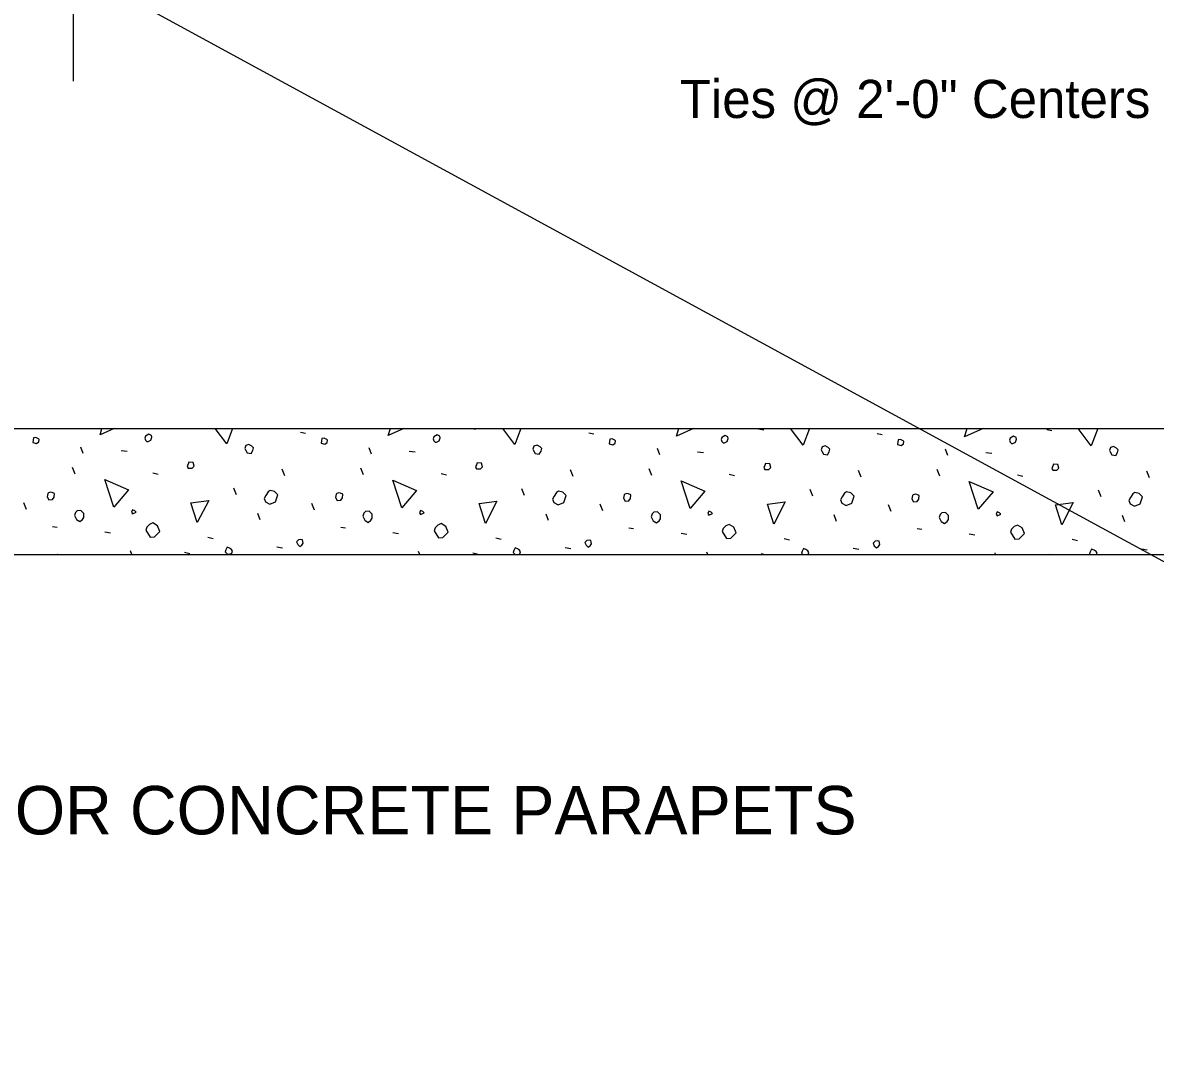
# Model space of a CAD drawing. Extents: x 110698 to 110915, y 110390 to 110472.
# Drawn here: x 110786.56 to 110792.55, y 110408.16 to 110413.66 of the extents above; entities that cross this region are included whole.
import ezdxf

# ---------------------------------------------------------------- set-up
doc = ezdxf.new("R2010")
doc.units = 0
for name, color, linetype in [('AdhocPoint_dp', 7, 'Continuous'), ('Border', 7, 'Continuous'), ('SheetBorder_dp', 7, 'Continuous'), ('SheetLines_dp', 7, 'Continuous')]:
    doc.layers.add(name, color=color, linetype=linetype)

msp = doc.modelspace()

# ---------------------------------------------------------------- linework, layer by layer
at = {"layer": 'AdhocPoint_dp'}
msp.add_line((110786.8255, 110421.2644), (110786.8255, 110413.3542), dxfattribs=at)
at = {"layer": 'SheetBorder_dp'}
for p, q in [((110787.4283, 110411.5179), (110787.4294, 110411.5177)), ((110788.0287, 110411.4982), (110788.0552, 110411.4929)), ((110788.9344, 110411.5179), (110788.9532, 110411.5141)), ((110789.5525, 110411.4947), (110789.579, 110411.4894)), ((110790.4505, 110411.5159), (110790.477, 110411.5106)), ((110791.0763, 110411.4911), (110791.1028, 110411.4858)), ((110791.9743, 110411.5124), (110792.0008, 110411.5071)), ((110786.8796, 110411.3851), (110786.8672, 110411.4187)), ((110788.4034, 110411.3815), (110788.391, 110411.4151)), ((110789.9272, 110411.378), (110789.9149, 110411.4116)), ((110791.451, 110411.3745), (110791.4387, 110411.4081)), ((110787.0794, 110411.401), (110787.1112, 110411.3975)), ((110788.6032, 110411.3975), (110788.635, 110411.3939)), ((110790.127, 110411.3939), (110790.1588, 110411.3904)), ((110791.6508, 110411.3904), (110791.6826, 110411.3869)), ((110786.8372, 110411.2755), (110786.823, 110411.3108)), ((110787.9456, 110411.2666), (110787.9314, 110411.302)), ((110788.361, 110411.2719), (110788.3469, 110411.3073)), ((110789.4694, 110411.2631), (110789.4552, 110411.2985)), ((110789.8848, 110411.2684), (110789.8707, 110411.3038)), ((110790.9932, 110411.2596), (110790.9791, 110411.2949)), ((110791.4086, 110411.2649), (110791.3945, 110411.3002)), ((110792.517, 110411.256), (110792.5029, 110411.2914)), ((110787.2473, 110411.2826), (110787.2756, 110411.2755)), ((110788.7711, 110411.279), (110788.7994, 110411.2719)), ((110790.2949, 110411.2755), (110790.3232, 110411.2684)), ((110791.8187, 110411.2719), (110791.847, 110411.2649)), ((110787.6892, 110411.1659), (110787.6751, 110411.2012)), ((110789.2131, 110411.1623), (110789.1989, 110411.1977)), ((110790.7369, 110411.1588), (110790.7227, 110411.1942)), ((110792.2607, 110411.1553), (110792.2465, 110411.1906)), ((110786.5791, 110411.0881), (110786.5649, 110411.1235)), ((110788.1029, 110411.0846), (110788.0888, 110411.1199)), ((110789.6267, 110411.081), (110789.6126, 110411.1164)), ((110791.1505, 110411.0775), (110791.1364, 110411.1128)), ((110787.8148, 110411.0333), (110787.8024, 110411.0669)), ((110789.3386, 110411.0298), (110789.3262, 110411.0634)), ((110790.8624, 110411.0262), (110790.85, 110411.0598)), ((110792.3862, 110411.0227), (110792.3738, 110411.0563)), ((110786.717, 110410.9997), (110786.7417, 110410.9962)), ((110788.2408, 110410.9962), (110788.2655, 110410.9926)), ((110789.7646, 110410.9926), (110789.7893, 110410.9891)), ((110791.2884, 110410.9891), (110791.3132, 110410.9856)), ((110786.9927, 110410.9714), (110787.0228, 110410.9661)), ((110787.5372, 110410.9431), (110787.5655, 110410.9361)), ((110788.5166, 110410.9679), (110788.5466, 110410.9626)), ((110789.061, 110410.9396), (110789.0893, 110410.9325)), ((110790.0404, 110410.9644), (110790.0704, 110410.9591)), ((110790.5848, 110410.9361), (110790.6131, 110410.929)), ((110791.5642, 110410.9608), (110791.5942, 110410.9555)), ((110792.1087, 110410.9325), (110792.1369, 110410.9255)), ((110787.136, 110410.8512), (110787.1289, 110410.8707)), ((110787.9031, 110410.8919), (110787.9332, 110410.8866)), ((110789.427, 110410.8883), (110789.457, 110410.883)), ((110790.9508, 110410.8848), (110790.9808, 110410.8795)), ((110792.4746, 110410.8813), (110792.5046, 110410.876)), ((110787.4152, 110410.8636), (110787.4435, 110410.8565)), ((110788.6585, 110410.8512), (110788.6527, 110410.8671)), ((110788.9391, 110410.8601), (110788.9673, 110410.853)), ((110790.181, 110410.8512), (110790.1765, 110410.8636)), ((110790.4629, 110410.8565), (110790.4841, 110410.8512)), ((110791.7036, 110410.8512), (110791.7003, 110410.8601)), ((110791.9867, 110410.853), (110791.9938, 110410.8512))]:
    msp.add_line(p, q, dxfattribs=at)
for points in [[(110786.6127, 110411.4434), (110786.6321, 110411.4381), (110786.6445, 110411.447), (110786.6463, 110411.4593), (110786.6427, 110411.4629), (110786.6286, 110411.4699), (110786.6162, 110411.4682), (110786.6144, 110411.4558), (110786.6127, 110411.4434)], [(110786.968, 110411.4841), (110786.9784, 110411.5179)], [(110787.0432, 110411.5179), (110786.968, 110411.4841)], [(110787.2155, 110411.4487), (110787.2226, 110411.4487), (110787.2367, 110411.4558), (110787.242, 110411.4717), (110787.2402, 110411.4805), (110787.2261, 110411.4876), (110787.2084, 110411.477), (110787.2049, 110411.4664), (110787.2084, 110411.4558), (110787.2155, 110411.4487)], [(110787.638, 110411.4363), (110787.576, 110411.5179)], [(110787.6684, 110411.5179), (110787.638, 110411.4363)], [(110788.4918, 110411.4805), (110788.5033, 110411.5179)], [(110788.5749, 110411.5179), (110788.4918, 110411.4805)], [(110788.7393, 110411.4452), (110788.7464, 110411.4452), (110788.7605, 110411.4523), (110788.7658, 110411.4682), (110788.764, 110411.477), (110788.7499, 110411.4841), (110788.7322, 110411.4735), (110788.7287, 110411.4629), (110788.7322, 110411.4523), (110788.7393, 110411.4452)], [(110789.1618, 110411.4328), (110789.0971, 110411.5179)], [(110789.1936, 110411.5179), (110789.1618, 110411.4328)], [(110790.0156, 110411.477), (110790.0282, 110411.5179)], [(110790.1066, 110411.5179), (110790.0156, 110411.477)], [(110790.2631, 110411.4417), (110790.2702, 110411.4417), (110790.2843, 110411.4487), (110790.2896, 110411.4646), (110790.2879, 110411.4735), (110790.2737, 110411.4805), (110790.256, 110411.4699), (110790.2525, 110411.4593), (110790.256, 110411.4487), (110790.2631, 110411.4417)], [(110790.6856, 110411.4293), (110790.6183, 110411.5179)], [(110790.7187, 110411.5179), (110790.6856, 110411.4293)], [(110791.5394, 110411.4735), (110791.5531, 110411.5179)], [(110791.6383, 110411.5179), (110791.5394, 110411.4735)], [(110791.7869, 110411.4381), (110791.794, 110411.4381), (110791.8081, 110411.4452), (110791.8134, 110411.4611), (110791.8117, 110411.4699), (110791.7975, 110411.477), (110791.7799, 110411.4664), (110791.7763, 110411.4558), (110791.7799, 110411.4452), (110791.7869, 110411.4381)], [(110792.2094, 110411.4257), (110792.1394, 110411.5179)], [(110792.2439, 110411.5179), (110792.2094, 110411.4257)], [(110787.737, 110411.4045), (110787.7458, 110411.3886), (110787.767, 110411.3851), (110787.7759, 110411.401), (110787.7794, 110411.4151), (110787.7706, 110411.424), (110787.7546, 110411.4328), (110787.7387, 110411.4275), (110787.7334, 110411.4116), (110787.737, 110411.4045)], [(110788.1365, 110411.4399), (110788.1559, 110411.4346), (110788.1683, 110411.4434), (110788.1701, 110411.4558), (110788.1665, 110411.4593), (110788.1524, 110411.4664), (110788.14, 110411.4646), (110788.1383, 110411.4523), (110788.1365, 110411.4399)], [(110789.2608, 110411.401), (110789.2696, 110411.3851), (110789.2908, 110411.3815), (110789.2997, 110411.3975), (110789.3032, 110411.4116), (110789.2944, 110411.4204), (110789.2785, 110411.4293), (110789.2626, 110411.424), (110789.2573, 110411.4081), (110789.2608, 110411.401)], [(110789.6603, 110411.4363), (110789.6797, 110411.431), (110789.6921, 110411.4399), (110789.6939, 110411.4523), (110789.6904, 110411.4558), (110789.6762, 110411.4629), (110789.6638, 110411.4611), (110789.6621, 110411.4487), (110789.6603, 110411.4363)], [(110790.7846, 110411.3975), (110790.7934, 110411.3815), (110790.8147, 110411.378), (110790.8235, 110411.3939), (110790.827, 110411.4081), (110790.8182, 110411.4169), (110790.8023, 110411.4257), (110790.7864, 110411.4204), (110790.7811, 110411.4045), (110790.7846, 110411.3975)], [(110791.1841, 110411.4328), (110791.2036, 110411.4275), (110791.2159, 110411.4363), (110791.2177, 110411.4487), (110791.2142, 110411.4523), (110791.2, 110411.4593), (110791.1877, 110411.4576), (110791.1859, 110411.4452), (110791.1841, 110411.4328)], [(110792.3084, 110411.3939), (110792.3173, 110411.378), (110792.3385, 110411.3745), (110792.3473, 110411.3904), (110792.3508, 110411.4045), (110792.342, 110411.4134), (110792.3261, 110411.4222), (110792.3102, 110411.4169), (110792.3049, 110411.401), (110792.3084, 110411.3939)], [(110787.4347, 110411.3073), (110787.4559, 110411.3073), (110787.4665, 110411.3179), (110787.4612, 110411.3374), (110787.4382, 110411.3391), (110787.4347, 110411.3285), (110787.4294, 110411.3197), (110787.4347, 110411.3073), (110787.4311, 110411.3108)], [(110788.9585, 110411.3038), (110788.9797, 110411.3038), (110788.9903, 110411.3144), (110788.985, 110411.3338), (110788.962, 110411.3356), (110788.9585, 110411.325), (110788.9532, 110411.3161), (110788.9585, 110411.3038), (110788.955, 110411.3073)], [(110790.4823, 110411.3002), (110790.5035, 110411.3002), (110790.5141, 110411.3108), (110790.5088, 110411.3303), (110790.4858, 110411.3321), (110790.4823, 110411.3214), (110790.477, 110411.3126), (110790.4823, 110411.3002), (110790.4788, 110411.3038)], [(110792.0061, 110411.2967), (110792.0273, 110411.2967), (110792.0379, 110411.3073), (110792.0326, 110411.3267), (110792.0097, 110411.3285), (110792.0061, 110411.3179), (110792.0008, 110411.3091), (110792.0061, 110411.2967), (110792.0026, 110411.3002)], [(110787.0405, 110411.1005), (110786.9927, 110411.2472), (110787.1183, 110411.1924), (110787.0405, 110411.1005)], [(110788.5643, 110411.0969), (110788.5166, 110411.2437), (110788.6421, 110411.1889), (110788.5643, 110411.0969)], [(110790.0881, 110411.0934), (110790.0404, 110411.2401), (110790.1659, 110411.1853), (110790.0881, 110411.0934)], [(110791.6119, 110411.0899), (110791.5642, 110411.2366), (110791.6897, 110411.1818), (110791.6119, 110411.0899)], [(110786.6887, 110411.1553), (110786.6975, 110411.1394), (110786.717, 110411.1411), (110786.7258, 110411.1535), (110786.7276, 110411.173), (110786.7152, 110411.1783), (110786.7064, 110411.18), (110786.6958, 110411.1765), (110786.6922, 110411.173), (110786.6887, 110411.1553)], [(110787.843, 110411.1288), (110787.866, 110411.1164), (110787.8961, 110411.1288), (110787.9084, 110411.1659), (110787.8908, 110411.1836), (110787.8678, 110411.1889), (110787.8572, 110411.1818), (110787.8448, 110411.1623), (110787.836, 110411.1464), (110787.843, 110411.1288)], [(110788.2125, 110411.1517), (110788.2213, 110411.1358), (110788.2408, 110411.1376), (110788.2496, 110411.15), (110788.2514, 110411.1694), (110788.239, 110411.1747), (110788.2302, 110411.1765), (110788.2196, 110411.173), (110788.216, 110411.1694), (110788.2125, 110411.1517)], [(110789.3669, 110411.1252), (110789.3898, 110411.1128), (110789.4199, 110411.1252), (110789.4323, 110411.1623), (110789.4146, 110411.18), (110789.3916, 110411.1853), (110789.381, 110411.1783), (110789.3686, 110411.1588), (110789.3598, 110411.1429), (110789.3669, 110411.1252)], [(110789.7363, 110411.1482), (110789.7452, 110411.1323), (110789.7646, 110411.1341), (110789.7734, 110411.1464), (110789.7752, 110411.1659), (110789.7628, 110411.1712), (110789.754, 110411.173), (110789.7434, 110411.1694), (110789.7399, 110411.1659), (110789.7363, 110411.1482)], [(110790.8907, 110411.1217), (110790.9136, 110411.1093), (110790.9437, 110411.1217), (110790.9561, 110411.1588), (110790.9384, 110411.1765), (110790.9154, 110411.1818), (110790.9048, 110411.1747), (110790.8924, 110411.1553), (110790.8836, 110411.1394), (110790.8907, 110411.1217)], [(110791.2601, 110411.1447), (110791.269, 110411.1288), (110791.2884, 110411.1305), (110791.2973, 110411.1429), (110791.299, 110411.1623), (110791.2866, 110411.1676), (110791.2778, 110411.1694), (110791.2672, 110411.1659), (110791.2637, 110411.1623), (110791.2601, 110411.1447)], [(110792.4145, 110411.1182), (110792.4375, 110411.1058), (110792.4675, 110411.1182), (110792.4799, 110411.1553), (110792.4622, 110411.173), (110792.4392, 110411.1783), (110792.4286, 110411.1712), (110792.4163, 110411.1517), (110792.4074, 110411.1358), (110792.4145, 110411.1182)], [(110787.4824, 110411.0192), (110787.4488, 110411.1235), (110787.5425, 110411.1358), (110787.4824, 110411.0192)], [(110789.0062, 110411.0156), (110788.9726, 110411.1199), (110789.0663, 110411.1323), (110789.0062, 110411.0156)], [(110790.53, 110411.0121), (110790.4965, 110411.1164), (110790.5901, 110411.1288), (110790.53, 110411.0121)], [(110792.0539, 110411.0085), (110792.0203, 110411.1128), (110792.114, 110411.1252), (110792.0539, 110411.0085)], [(110786.8336, 110411.0563), (110786.8442, 110411.0351), (110786.8619, 110411.0245), (110786.8761, 110411.0351), (110786.8831, 110411.0457), (110786.8831, 110411.0669), (110786.8672, 110411.0828), (110786.8478, 110411.081), (110786.8389, 110411.0722), (110786.8336, 110411.0563)], [(110787.1395, 110411.0651), (110787.1589, 110411.074), (110787.1518, 110411.081), (110787.1395, 110411.0863), (110787.1342, 110411.074), (110787.1395, 110411.0651)], [(110788.3575, 110411.0527), (110788.3681, 110411.0315), (110788.3857, 110411.0209), (110788.3999, 110411.0315), (110788.407, 110411.0421), (110788.407, 110411.0634), (110788.391, 110411.0793), (110788.3716, 110411.0775), (110788.3628, 110411.0687), (110788.3575, 110411.0527)], [(110788.6633, 110411.0616), (110788.6827, 110411.0704), (110788.6757, 110411.0775), (110788.6633, 110411.0828), (110788.658, 110411.0704), (110788.6633, 110411.0616)], [(110789.8813, 110411.0492), (110789.8919, 110411.028), (110789.9096, 110411.0174), (110789.9237, 110411.028), (110789.9308, 110411.0386), (110789.9308, 110411.0598), (110789.9149, 110411.0757), (110789.8954, 110411.074), (110789.8866, 110411.0651), (110789.8813, 110411.0492)], [(110790.1871, 110411.058), (110790.2065, 110411.0669), (110790.1995, 110411.074), (110790.1871, 110411.0793), (110790.1818, 110411.0669), (110790.1871, 110411.058)], [(110791.4051, 110411.0457), (110791.4157, 110411.0245), (110791.4334, 110411.0139), (110791.4475, 110411.0245), (110791.4546, 110411.0351), (110791.4546, 110411.0563), (110791.4387, 110411.0722), (110791.4192, 110411.0704), (110791.4104, 110411.0616), (110791.4051, 110411.0457)], [(110791.7109, 110411.0545), (110791.7304, 110411.0634), (110791.7233, 110411.0704), (110791.7109, 110411.0757), (110791.7056, 110411.0634), (110791.7109, 110411.0545)], [(110787.2102, 110410.9803), (110787.2332, 110410.9431), (110787.2561, 110410.9449), (110787.265, 110410.9537), (110787.2844, 110410.9732), (110787.272, 110411.0032), (110787.2473, 110411.0174), (110787.2296, 110411.0103), (110787.2155, 110410.9962), (110787.2102, 110410.9803)], [(110788.734, 110410.9767), (110788.757, 110410.9396), (110788.78, 110410.9414), (110788.7888, 110410.9502), (110788.8082, 110410.9697), (110788.7959, 110410.9997), (110788.7711, 110411.0139), (110788.7534, 110411.0068), (110788.7393, 110410.9926), (110788.734, 110410.9767)], [(110790.2578, 110410.9732), (110790.2808, 110410.9361), (110790.3038, 110410.9378), (110790.3126, 110410.9467), (110790.3321, 110410.9661), (110790.3197, 110410.9962), (110790.2949, 110411.0103), (110790.2773, 110411.0032), (110790.2631, 110410.9891), (110790.2578, 110410.9732)], [(110791.7816, 110410.9697), (110791.8046, 110410.9325), (110791.8276, 110410.9343), (110791.8364, 110410.9431), (110791.8559, 110410.9626), (110791.8435, 110410.9926), (110791.8187, 110411.0068), (110791.8011, 110410.9997), (110791.7869, 110410.9856), (110791.7816, 110410.9697)], [(110788.0145, 110410.9043), (110788.0251, 110410.8936), (110788.0357, 110410.9007), (110788.0428, 110410.9113), (110788.0393, 110410.929), (110788.0304, 110410.9308), (110788.018, 110410.929), (110788.0074, 110410.9184), (110788.0145, 110410.9043)], [(110787.6397, 110410.8548), (110787.6521, 110410.853), (110787.6645, 110410.8583), (110787.668, 110410.8689), (110787.6627, 110410.8777), (110787.6521, 110410.8848), (110787.6397, 110410.8901), (110787.6327, 110410.876), (110787.6291, 110410.8654), (110787.6397, 110410.8548)], [(110789.1801, 110410.8512), (110789.1883, 110410.8548), (110789.1918, 110410.8654), (110789.1865, 110410.8742), (110789.1759, 110410.8813), (110789.1636, 110410.8866), (110789.1565, 110410.8724), (110789.153, 110410.8618), (110789.1636, 110410.8512)], [(110789.5383, 110410.9007), (110789.5489, 110410.8901), (110789.5595, 110410.8972), (110789.5666, 110410.9078), (110789.5631, 110410.9255), (110789.5542, 110410.9272), (110789.5419, 110410.9255), (110789.5313, 110410.9149), (110789.5383, 110410.9007)], [(110790.7121, 110410.8512), (110790.7157, 110410.8618), (110790.7104, 110410.8707), (110790.6997, 110410.8777), (110790.6874, 110410.883), (110790.6803, 110410.8689), (110790.6768, 110410.8583), (110790.6838, 110410.8512)], [(110791.0621, 110410.8972), (110791.0727, 110410.8866), (110791.0834, 110410.8936), (110791.0904, 110410.9043), (110791.0869, 110410.9219), (110791.0781, 110410.9237), (110791.0657, 110410.9219), (110791.0551, 110410.9113), (110791.0621, 110410.8972)], [(110792.2371, 110410.8512), (110792.2395, 110410.8583), (110792.2342, 110410.8671), (110792.2236, 110410.8742), (110792.2112, 110410.8795), (110792.2041, 110410.8654), (110792.2006, 110410.8548), (110792.2041, 110410.8512)], [(110786.7448, 110410.8512), (110786.7435, 110410.853), (110786.9432, 110410.8512)]]:
    msp.add_lwpolyline(points, dxfattribs=at)
at = {"layer": 'SheetLines_dp'}
for p, q in [((110767.7236, 110424.3517), (110816.3335, 110397.8895)), ((110775.4386, 110411.5179), (110798.2125, 110411.5179)), ((110775.4386, 110410.8512), (110798.2125, 110410.8512))]:
    msp.add_line(p, q, dxfattribs=at)

# ---------------------------------------------------------------- texts
at = {"layer": 'Border'}
for s, height, p in [('Ties @ 2\'-0" Centers', 0.2016, (110790.0333, 110413.1587)), ('PULL POST ASSEMBLY DETAIL FOR CONCRETE PARAPETS', 0.256001, (110781.0954, 110409.3712))]:
    msp.add_text(s, height=height, dxfattribs=at).set_placement(p)

doc.saveas('drawing.dxf')
